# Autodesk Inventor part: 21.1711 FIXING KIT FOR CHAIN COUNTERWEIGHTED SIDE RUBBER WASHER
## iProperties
Created: 2007-05
Part Number: 21.1711 FIXING KIT FOR CHAIN COUNTERWEIGHTED SIDE RUBBER WASHER
Document SubType Name: Modeling
Designer: Andy Moles
Material: Rubber
Mass: 2.0187 g
Surface Area: 13.9447 cm^2
Volume: 2.17064 cm^3
Density: 0.93 g/cm^3
Author: Andy Moles
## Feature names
1. Extrusion1
